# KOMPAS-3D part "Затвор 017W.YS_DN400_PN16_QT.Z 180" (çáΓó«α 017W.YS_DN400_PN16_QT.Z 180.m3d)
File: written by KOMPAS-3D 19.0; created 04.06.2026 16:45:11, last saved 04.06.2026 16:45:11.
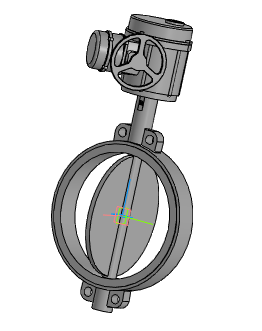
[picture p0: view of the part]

Document properties: Автор: Энергия; Полное имя файла: ..\..\..\3d для проектировщиков\017W разные\x.x Тип 017W.Y(S) Затвор дисковый поворотный межфланцевый\Затвор 017W.Y(S)_DN32-DN450_QT.Z\Затвор 017W.Y_DN400_PN16_QT.Z 180.a3d

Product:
- Part/product: Затвор 017W.YS_DN400_PN16_QT.Z 180
    Масса: 136.786

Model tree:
1. Операция без истории:1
